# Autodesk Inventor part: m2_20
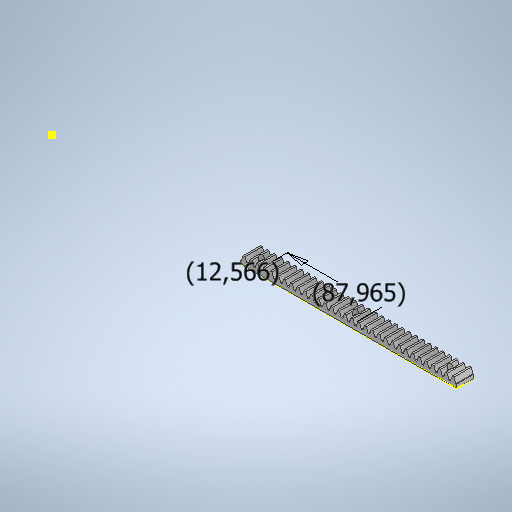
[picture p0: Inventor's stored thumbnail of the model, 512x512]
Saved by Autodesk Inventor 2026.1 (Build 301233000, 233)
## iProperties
Created: 2025-11
Part Number: m2_20
Material: Steel
Document SubType Name: Modeling
Designer: Yury Melnikov
Density: 7.85 g/cm^3
Appearance: По умолчанию
Title: m2_20.step
Sending System: Autodesk Translation Framework v14.17.0.0
Preprocessor: ST-DEVELOPER v20.1
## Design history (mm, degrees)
feature "Body3"
sketch "Эскиз1"
  geometry: L1 (0, 0)-(201.062, 0) reference; L2 (201.062, 0)-(201.062, 16) reference; L3 (0, 16)-(201.062, 16) reference; L4 (0, 0)-(0, 16) reference; C1 r 1.35 at (12.566, 8) reference; C2 r 1.35 at (100.531, 8) reference; C3 r 1.35 at (188.496, 8) reference; 1 further point
  dimensions: "d0" = 87.96459 distance of C2.centre C1.centre (derived); "d1" = 12.56644 distance from line of L4 C1.centre (derived)
  node "Спроецированная петля1"
node "Твердое тело1"
